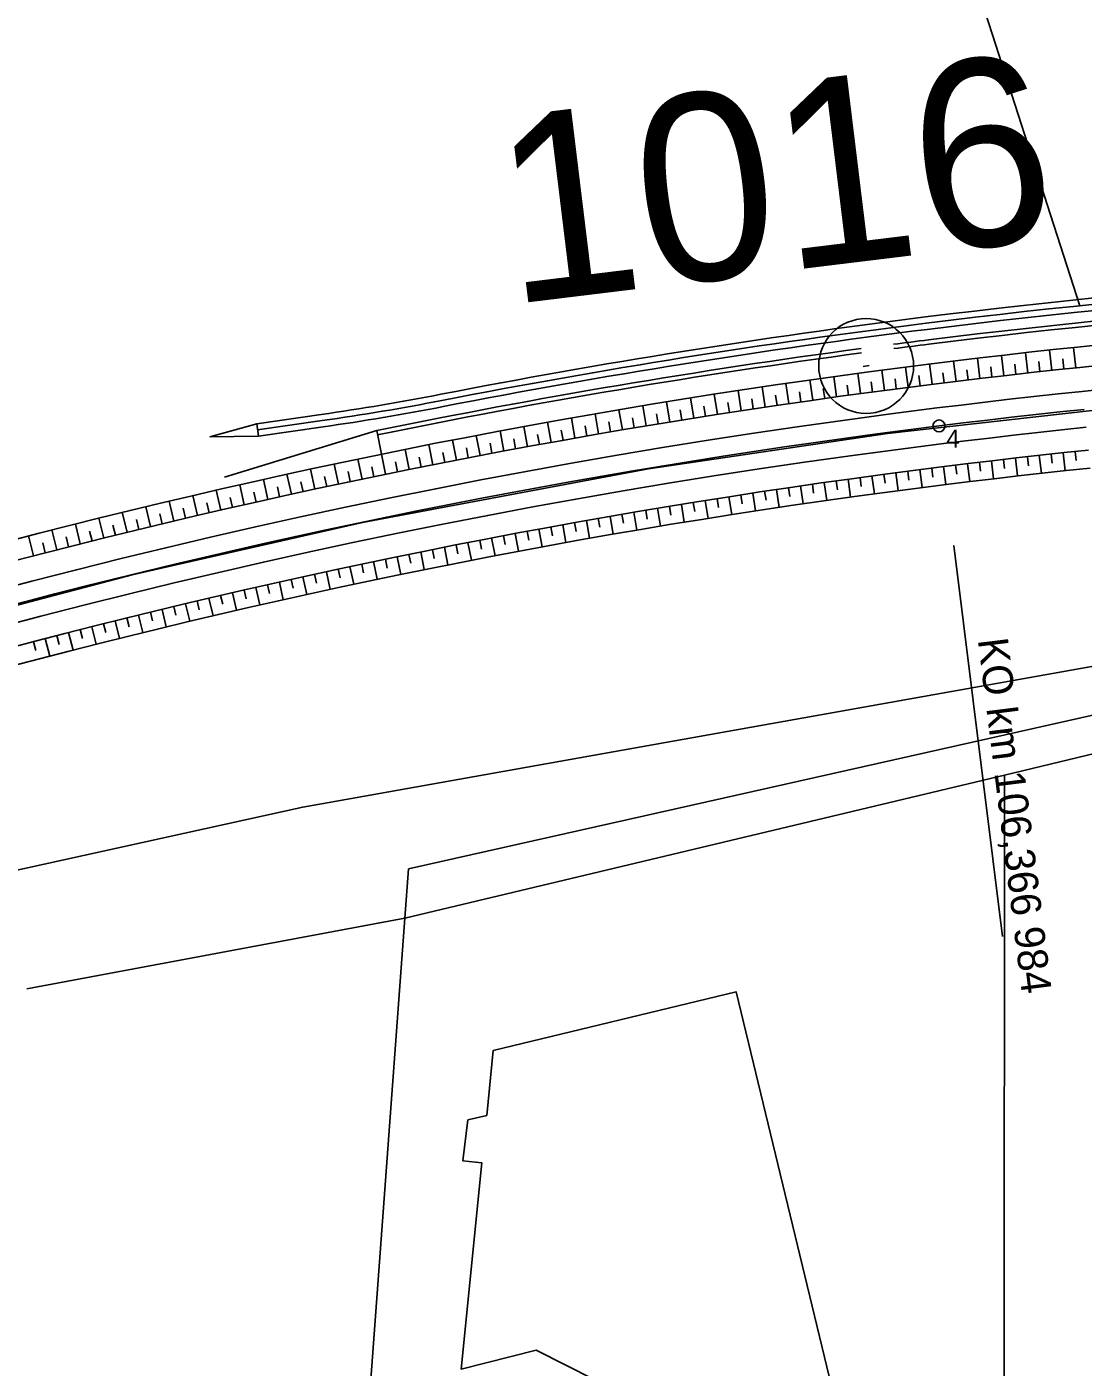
# Model space of a CAD drawing. Extents: x -758836 to -757729, y -1175316 to -1174366.
# Drawn here: x -758279.4 to -758235.6, y -1174806.2 to -1174750.5 of the extents above; entities that cross this region are included whole.
import ezdxf

# ---------------------------------------------------------------- set-up
doc = ezdxf.new("R2010")
doc.units = 0
for name, color, linetype in [('_NOR-návrh tenká', 7, 'Continuous'), ('_NOR-osa', 7, 'Continuous'), ('_NOR-popis', 7, 'Continuous'), ('_NOR-svahy', 7, 'Continuous'), ('_NOR-vytyčení', 7, 'Continuous'), ('G_Obvod stavby', 7, 'Continuous'), ('Hranice parcel', 7, 'Continuous'), ('Vrstva 1', 7, 'Continuous'), ('Vrstva 63', 7, 'Continuous')]:
    doc.layers.add(name, color=color, linetype=linetype)

# ---------------------------------------------------------------- blocks, each defined once
blk = doc.blocks.new('POINT_DISPLAY')
blk.add_line((0, 0), (0, 0))
blk = doc.blocks.new('C015_1')
at = {"layer": 'Vrstva 63'}
blk.add_line((-0.05, 0), (0.05, 0), dxfattribs=at)
blk.add_circle((0, 0), 0.756, dxfattribs=at)

msp = doc.modelspace()

# ---------------------------------------------------------------- linework, layer by layer
at = {"layer": '_NOR-návrh tenká'}
for p, q in [((-758271.812, -1174767.556), (-758269.869, -1174767.016)), ((-758269.869, -1174767.016), (-758269.795, -1174767.531)), ((-758269.795, -1174767.531), (-758271.812, -1174767.556)), ((-758271.211, -1174769.241), (-758264.887, -1174767.303)), ((-758264.887, -1174767.303), (-758264.686, -1174768.283))]:
    msp.add_line(p, q, dxfattribs=at)
for points in [[(-758242.105, -1174762.587), (-758241.09, -1174762.463), (-758240.072, -1174762.341), (-758239.053, -1174762.223), (-758238.033, -1174762.108), (-758237.014, -1174761.997), (-758235.995, -1174761.888), (-758234.975, -1174761.783)], [(-758242.073, -1174762.845), (-758241.059, -1174762.721), (-758240.041, -1174762.599), (-758239.023, -1174762.481), (-758238.005, -1174762.366), (-758236.986, -1174762.255), (-758235.968, -1174762.147), (-758234.949, -1174762.042)], [(-758242.041, -1174763.103), (-758241.028, -1174762.979), (-758240.011, -1174762.857), (-758238.994, -1174762.739), (-758237.976, -1174762.625), (-758236.958, -1174762.514), (-758235.941, -1174762.406), (-758234.923, -1174762.301)], [(-758241.988, -1174763.537), (-758240.975, -1174763.413), (-758239.96, -1174763.291), (-758238.944, -1174763.174), (-758237.928, -1174763.059), (-758236.912, -1174762.948), (-758235.895, -1174762.84), (-758234.879, -1174762.735)], [(-758241.966, -1174763.716), (-758240.954, -1174763.591), (-758239.939, -1174763.47), (-758238.923, -1174763.352), (-758237.908, -1174763.238), (-758236.892, -1174763.127), (-758235.877, -1174763.019), (-758234.861, -1174762.915)], [(-758241.865, -1174764.529), (-758240.855, -1174764.405), (-758239.843, -1174764.285), (-758238.83, -1174764.167), (-758237.818, -1174764.053), (-758236.804, -1174763.942), (-758235.791, -1174763.835), (-758234.778, -1174763.73)], [(-758241.761, -1174765.373), (-758240.753, -1174765.249), (-758239.744, -1174765.129), (-758238.734, -1174765.012), (-758237.724, -1174764.898), (-758236.713, -1174764.787), (-758235.703, -1174764.68), (-758234.692, -1174764.576)], [(-758241.638, -1174766.365), (-758240.633, -1174766.242), (-758239.627, -1174766.122), (-758238.62, -1174766.005), (-758237.613, -1174765.892), (-758236.606, -1174765.782), (-758235.599, -1174765.675), (-758234.591, -1174765.571)], [(-758269.869, -1174767.016), (-758267.19, -1174766.633)], [(-758269.832, -1174767.273), (-758267.154, -1174766.89)], [(-758269.795, -1174767.531), (-758267.117, -1174767.148)], [(-758241.454, -1174767.854), (-758240.453, -1174767.731), (-758239.452, -1174767.612), (-758238.45, -1174767.496), (-758237.448, -1174767.383), (-758236.446, -1174767.273), (-758235.443, -1174767.167)], [(-758241.337, -1174768.797), (-758240.338, -1174768.674), (-758239.341, -1174768.555), (-758238.342, -1174768.439), (-758237.343, -1174768.327), (-758236.344, -1174768.218), (-758235.344, -1174768.111)], [(-758241.245, -1174769.541), (-758240.248, -1174769.419), (-758239.253, -1174769.3), (-758238.257, -1174769.185), (-758237.26, -1174769.072), (-758236.263, -1174768.963), (-758235.266, -1174768.857)]]:
    msp.add_lwpolyline(points, dxfattribs=at)
for centre, radius, start, end in [((-758205.34, -1175057.864), 297.557, 97.09744, 101.02201), ((-758205.34, -1175057.864), 297.297, 97.09748, 101.02201), ((-758205.34, -1175057.864), 297.037, 97.09752, 101.02201), ((-758205.34, -1175057.864), 296.6, 97.09759, 97.37991), ((-758205.34, -1175057.864), 296.42, 97.09762, 97.38099), ((-758205.34, -1175057.864), 296.6, 97.64234, 101.58164), ((-758205.34, -1175057.864), 296.42, 97.64296, 101.58164), ((-758205.34, -1175057.864), 295.6, 97.09776, 129.28488), ((-758205.34, -1175057.864), 294.75, 97.0979, 129.28474), ((-758281.298, -1174667.896), 99.74, 278.13115, 281.02201), ((-758205.34, -1175057.864), 293.75, 97.09807, 120.96729), ((-758281.298, -1174667.896), 100, 278.13115, 281.02201), ((-758281.298, -1174667.896), 100.26, 278.13115, 281.02201), ((-758205.34, -1175057.864), 292.25, 97.09832, 120.96729), ((-758205.34, -1175057.864), 291.3, 97.09848, 129.28417), ((-758205.34, -1175057.864), 290.55, 97.09861, 129.28404)]:
    msp.add_arc(centre, radius, start, end, dxfattribs=at)
at = {"layer": '_NOR-osa'}
msp.add_lwpolyline([(-758235.521, -1174766.421), (-758236.526, -1174766.527), (-758237.531, -1174766.637), (-758238.535, -1174766.75), (-758239.539, -1174766.867), (-758240.543, -1174766.987), (-758241.546, -1174767.11)], dxfattribs=at)
msp.add_circle((-758241.546, -1174767.11), 0.25, dxfattribs=at)
msp.add_arc((-758205.34, -1175057.864), 293, 97.09819, 129.28445, dxfattribs=at)
at = {"layer": '_NOR-popis'}
msp.add_line((-758240.928, -1174772.071), (-758238.907, -1174788.304), dxfattribs=at)
msp.add_lwpolyline([(-758240.814, -1174715.275), (-758249.857, -1174718.187), (-758235.706, -1174762.12)], dxfattribs=at)
at = {"layer": '_NOR-svahy'}
for points in [[(-758239.845, -1174765.141), (-758239.946, -1174764.297)], [(-758238.852, -1174765.025), (-758238.95, -1174764.181)], [(-758237.858, -1174764.913), (-758237.953, -1174764.068)], [(-758236.864, -1174764.804), (-758236.956, -1174763.959)], [(-758236.367, -1174764.751), (-758236.412, -1174764.328)], [(-758235.87, -1174764.698), (-758235.959, -1174763.853)], [(-758243.814, -1174765.636), (-758243.925, -1174764.793)], [(-758242.823, -1174765.507), (-758242.931, -1174764.664)], [(-758241.83, -1174765.382), (-758241.936, -1174764.538)], [(-758241.334, -1174765.321), (-758241.386, -1174764.899)], [(-758240.838, -1174765.26), (-758240.942, -1174764.416)], [(-758240.342, -1174765.2), (-758240.392, -1174764.778)], [(-758239.348, -1174765.083), (-758239.397, -1174764.661)], [(-758238.355, -1174764.969), (-758238.402, -1174764.547)], [(-758237.361, -1174764.858), (-758237.407, -1174764.436)], [(-758247.776, -1174766.185), (-758247.899, -1174765.344)], [(-758246.787, -1174766.043), (-758246.906, -1174765.201)], [(-758245.796, -1174765.904), (-758245.913, -1174765.062)], [(-758245.301, -1174765.836), (-758245.359, -1174765.414)], [(-758244.805, -1174765.768), (-758244.919, -1174764.926)], [(-758244.31, -1174765.702), (-758244.366, -1174765.28)], [(-758243.318, -1174765.571), (-758243.373, -1174765.15)], [(-758242.327, -1174765.444), (-758242.38, -1174765.022)], [(-758251.731, -1174766.788), (-758251.864, -1174765.948)], [(-758250.743, -1174766.632), (-758250.874, -1174765.792)], [(-758249.755, -1174766.48), (-758249.883, -1174765.639)], [(-758249.26, -1174766.405), (-758249.323, -1174765.984)], [(-758248.766, -1174766.331), (-758248.891, -1174765.49)], [(-758248.271, -1174766.257), (-758248.333, -1174765.837)], [(-758247.282, -1174766.113), (-758247.342, -1174765.693)], [(-758246.291, -1174765.973), (-758246.35, -1174765.552)], [(-758254.691, -1174767.275), (-758254.833, -1174766.437)], [(-758253.705, -1174767.109), (-758253.844, -1174766.271)], [(-758252.718, -1174766.947), (-758252.855, -1174766.108)], [(-758252.224, -1174766.867), (-758252.292, -1174766.447)], [(-758251.237, -1174766.709), (-758251.303, -1174766.29)], [(-758250.249, -1174766.555), (-758250.314, -1174766.135)], [(-758258.63, -1174767.971), (-758258.783, -1174767.135)], [(-758257.646, -1174767.792), (-758257.797, -1174766.956)], [(-758256.661, -1174767.617), (-758256.809, -1174766.78)], [(-758256.169, -1174767.53), (-758256.242, -1174767.111)], [(-758255.676, -1174767.444), (-758255.822, -1174766.607)], [(-758255.184, -1174767.359), (-758255.256, -1174766.94)], [(-758254.198, -1174767.192), (-758254.268, -1174766.773)], [(-758253.211, -1174767.028), (-758253.28, -1174766.608)], [(-758261.577, -1174768.529), (-758261.74, -1174767.694)], [(-758260.595, -1174768.34), (-758260.755, -1174767.505)], [(-758259.613, -1174768.154), (-758259.769, -1174767.318)], [(-758259.121, -1174768.062), (-758259.199, -1174767.644)], [(-758258.138, -1174767.881), (-758258.214, -1174767.463)], [(-758257.154, -1174767.704), (-758257.228, -1174767.286)], [(-758263.539, -1174768.917), (-758263.707, -1174768.084)], [(-758262.559, -1174768.721), (-758262.724, -1174767.887)], [(-758262.068, -1174768.625), (-758262.15, -1174768.208)], [(-758261.087, -1174768.434), (-758261.167, -1174768.017)], [(-758260.104, -1174768.246), (-758260.183, -1174767.829)], [(-758236.387, -1174768.222), (-758236.306, -1174768.968)], [(-758235.89, -1174768.169), (-758235.851, -1174768.542)], [(-758266.477, -1174769.524), (-758266.654, -1174768.693)], [(-758265.499, -1174769.319), (-758265.672, -1174768.487)], [(-758265.009, -1174769.217), (-758265.095, -1174768.801)], [(-758264.519, -1174769.116), (-758264.69, -1174768.284)], [(-758264.029, -1174769.016), (-758264.114, -1174768.6)], [(-758263.049, -1174768.819), (-758263.132, -1174768.402)], [(-758241.354, -1174768.799), (-758241.261, -1174769.543)], [(-758240.858, -1174768.738), (-758240.812, -1174769.11)], [(-758240.362, -1174768.677), (-758240.27, -1174769.421)], [(-758239.865, -1174768.618), (-758239.821, -1174768.99)], [(-758239.369, -1174768.558), (-758239.28, -1174769.303)], [(-758238.872, -1174768.501), (-758238.829, -1174768.873)], [(-758238.375, -1174768.443), (-758238.289, -1174769.188)], [(-758237.878, -1174768.387), (-758237.836, -1174768.76)], [(-758237.382, -1174768.331), (-758237.298, -1174769.076)], [(-758236.885, -1174768.277), (-758236.844, -1174768.649)], [(-758269.409, -1174770.162), (-758269.594, -1174769.332)], [(-758268.432, -1174769.946), (-758268.614, -1174769.116)], [(-758267.455, -1174769.733), (-758267.634, -1174768.903)], [(-758266.966, -1174769.629), (-758267.055, -1174769.213)], [(-758265.988, -1174769.421), (-758266.075, -1174769.005)], [(-758245.32, -1174769.321), (-758245.217, -1174770.064)], [(-758244.825, -1174769.253), (-758244.774, -1174769.624)], [(-758244.329, -1174769.185), (-758244.229, -1174769.928)], [(-758243.834, -1174769.119), (-758243.784, -1174769.49)], [(-758243.338, -1174769.053), (-758243.24, -1174769.797)], [(-758242.842, -1174768.988), (-758242.794, -1174769.36)], [(-758242.346, -1174768.924), (-758242.251, -1174769.668)], [(-758241.85, -1174768.861), (-758241.803, -1174769.233)], [(-758271.359, -1174770.603), (-758271.55, -1174769.775)], [(-758270.385, -1174770.381), (-758270.572, -1174769.552)], [(-758269.897, -1174770.271), (-758269.99, -1174769.856)], [(-758268.921, -1174770.053), (-758269.012, -1174769.638)], [(-758267.944, -1174769.839), (-758268.034, -1174769.424)], [(-758249.278, -1174769.897), (-758249.165, -1174770.638)], [(-758248.784, -1174769.822), (-758248.728, -1174770.193)], [(-758248.289, -1174769.748), (-758248.179, -1174770.49)], [(-758247.795, -1174769.674), (-758247.74, -1174770.045)], [(-758247.3, -1174769.602), (-758247.192, -1174770.344)], [(-758246.805, -1174769.53), (-758246.752, -1174769.902)], [(-758246.31, -1174769.46), (-758246.205, -1174770.202)], [(-758245.815, -1174769.39), (-758245.763, -1174769.761)], [(-758274.28, -1174771.29), (-758274.479, -1174770.463)], [(-758273.307, -1174771.058), (-758273.503, -1174770.23)], [(-758272.334, -1174770.829), (-758272.527, -1174770.001)], [(-758271.847, -1174770.715), (-758271.943, -1174770.301)], [(-758270.872, -1174770.491), (-758270.967, -1174770.077)], [(-758252.735, -1174770.446), (-758252.674, -1174770.816)], [(-758252.241, -1174770.365), (-758252.121, -1174771.105)], [(-758251.748, -1174770.285), (-758251.688, -1174770.655)], [(-758251.254, -1174770.205), (-758251.136, -1174770.946)], [(-758250.76, -1174770.127), (-758250.702, -1174770.497)], [(-758250.266, -1174770.049), (-758250.151, -1174770.79)], [(-758249.772, -1174769.973), (-758249.715, -1174770.343)], [(-758276.223, -1174771.764), (-758276.427, -1174770.939)], [(-758275.252, -1174771.525), (-758275.453, -1174770.7)], [(-758274.766, -1174771.407), (-758274.866, -1174770.994)], [(-758273.794, -1174771.173), (-758273.892, -1174770.76)], [(-758272.821, -1174770.943), (-758272.918, -1174770.529)], [(-758256.185, -1174771.036), (-758256.054, -1174771.774)], [(-758255.692, -1174770.949), (-758255.627, -1174771.318)], [(-758255.2, -1174770.863), (-758255.071, -1174771.602)], [(-758254.707, -1174770.778), (-758254.643, -1174771.147)], [(-758254.214, -1174770.693), (-758254.088, -1174771.433)], [(-758253.721, -1174770.61), (-758253.659, -1174770.98)], [(-758253.228, -1174770.527), (-758253.105, -1174771.267)], [(-758278.162, -1174772.252), (-758278.372, -1174771.428)], [(-758277.193, -1174772.006), (-758277.4, -1174771.182)], [(-758276.708, -1174771.885), (-758276.811, -1174771.472)], [(-758275.737, -1174771.644), (-758275.839, -1174771.232)], [(-758259.136, -1174771.575), (-758258.997, -1174772.312)], [(-758258.644, -1174771.483), (-758258.576, -1174771.851)], [(-758258.153, -1174771.392), (-758258.017, -1174772.129)], [(-758257.661, -1174771.301), (-758257.594, -1174771.67)], [(-758257.169, -1174771.212), (-758257.036, -1174771.95)], [(-758256.677, -1174771.123), (-758256.611, -1174771.493)], [(-758279.131, -1174772.5), (-758279.344, -1174771.677)], [(-758278.647, -1174772.376), (-758278.752, -1174771.964)], [(-758277.678, -1174772.129), (-758277.782, -1174771.717)], [(-758262.081, -1174772.144), (-758261.935, -1174772.879)], [(-758261.591, -1174772.047), (-758261.518, -1174772.415)], [(-758261.1, -1174771.951), (-758260.957, -1174772.687)], [(-758260.609, -1174771.855), (-758260.538, -1174772.224)], [(-758260.118, -1174771.761), (-758259.977, -1174772.498)], [(-758259.627, -1174771.667), (-758259.557, -1174772.036)], [(-758264.531, -1174772.641), (-758264.455, -1174773.008)], [(-758264.042, -1174772.54), (-758263.891, -1174773.275)], [(-758263.552, -1174772.44), (-758263.477, -1174772.807)], [(-758263.062, -1174772.34), (-758262.913, -1174773.075)], [(-758262.572, -1174772.242), (-758262.498, -1174772.609)], [(-758267.466, -1174773.266), (-758267.386, -1174773.632)], [(-758266.977, -1174773.16), (-758266.818, -1174773.893)], [(-758266.488, -1174773.054), (-758266.41, -1174773.421)], [(-758265.999, -1174772.95), (-758265.843, -1174773.683)], [(-758265.51, -1174772.846), (-758265.433, -1174773.213)], [(-758265.021, -1174772.743), (-758264.867, -1174773.477)], [(-758269.906, -1174773.81), (-758269.74, -1174774.541)], [(-758269.418, -1174773.699), (-758269.336, -1174774.065)], [(-758268.93, -1174773.59), (-758268.767, -1174774.322)], [(-758268.442, -1174773.481), (-758268.361, -1174773.847)], [(-758267.954, -1174773.373), (-758267.793, -1174774.106)], [(-758272.341, -1174774.374), (-758272.255, -1174774.739)], [(-758271.854, -1174774.26), (-758271.683, -1174774.99)], [(-758271.368, -1174774.146), (-758271.283, -1174774.511)], [(-758270.88, -1174774.033), (-758270.712, -1174774.764)], [(-758270.393, -1174773.921), (-758270.309, -1174774.286)], [(-758274.286, -1174774.841), (-758274.197, -1174775.205)], [(-758273.8, -1174774.723), (-758273.624, -1174775.452)], [(-758273.314, -1174774.606), (-758273.226, -1174774.971)], [(-758272.828, -1174774.49), (-758272.654, -1174775.219)], [(-758276.712, -1174775.443), (-758276.529, -1174776.17)], [(-758276.227, -1174775.321), (-758276.136, -1174775.685)], [(-758275.742, -1174775.2), (-758275.561, -1174775.927)], [(-758275.257, -1174775.079), (-758275.167, -1174775.443)], [(-758274.772, -1174774.96), (-758274.593, -1174775.688)], [(-758278.65, -1174775.94), (-758278.461, -1174776.666)], [(-758278.166, -1174775.814), (-758278.072, -1174776.177)], [(-758277.681, -1174775.69), (-758277.495, -1174776.416)], [(-758277.197, -1174775.566), (-758277.104, -1174775.929)], [(-758279.133, -1174776.066), (-758279.038, -1174776.429)]]:
    msp.add_lwpolyline(points, dxfattribs=at)
at = {"layer": 'G_Obvod stavby'}
msp.add_lwpolyline([(-758392.72, -1174840.756), (-758391.23, -1174838.56), (-758368.37, -1174821.64), (-758340.31, -1174807.33), (-758320.27, -1174796.89), (-758301, -1174790.21), (-758267.96, -1174782.93), (-758224.96, -1174775.27), (-758184.87, -1174772.83), (-758142.71, -1174770.26), (-758089.84, -1174768.68), (-758106.02, -1174731.44), (-758149.09, -1174725.67), (-758199.62, -1174726.6), (-758225.76, -1174732.36), (-758252.17, -1174738.18), (-758254.97, -1174739.34), (-758266.58, -1174744.16), (-758279.45, -1174749.49), (-758302.42, -1174759.02), (-758331.68, -1174770.24), (-758367.17, -1174799.81), (-758405.64, -1174832.2)], dxfattribs=at)
at = {"layer": 'Hranice parcel'}
for p, q in [((-758225.62, -1174776.96), (-758263.57, -1174785.5)), ((-758238.83, -1174781.6), (-758263.72, -1174787.54)), ((-758238.83, -1174781.6), (-758238.86, -1174825.45)), ((-758263.57, -1174785.5), (-758263.72, -1174787.54)), ((-758263.72, -1174787.54), (-758279.42, -1174790.47)), ((-758263.72, -1174787.54), (-758266.21, -1174821.26))]:
    msp.add_line(p, q, dxfattribs=at)
for points in [[(-758184.87, -1174772.83), (-758224.96, -1174775.27), (-758267.96, -1174782.93), (-758301, -1174790.21), (-758320.27, -1174796.89)], [(-758225.53, -1174779.72), (-758235.04, -1174780.69), (-758238.83, -1174781.6)], [(-758261.31, -1174797.61), (-758261.1, -1174795.92), (-758260.32, -1174795.73), (-758260.05, -1174793.03), (-758249.97, -1174790.6), (-758245.99, -1174807.02), (-758245.12, -1174810.68), (-758252.37, -1174812.37), (-758253.43, -1174807.62), (-758255.84, -1174806.71), (-758258.27, -1174805.48), (-758261.38, -1174806.26), (-758260.52, -1174797.7), (-758261.31, -1174797.61)]]:
    msp.add_lwpolyline(points, dxfattribs=at)
at = {"layer": 'Vrstva 1'}
for points in [[(-758275.047, -1174773.289), (-758265.484, -1174771.118), (-758253.61, -1174768.888), (-758243.69, -1174767.426), (-758231.371, -1174766.042), (-758219.363, -1174765.122), (-758206.915, -1174764.505), (-758194.225, -1174764.118), (-758182.013, -1174763.871), (-758170.862, -1174763.683), (-758162.019, -1174763.496), (-758153.195, -1174763.228), (-758152.069, -1174763.19), (-758141.836, -1174762.716), (-758130.402, -1174761.933), (-758120.726, -1174760.981), (-758108.612, -1174759.398), (-758096.467, -1174757.277), (-758085.591, -1174754.917)], [(-758443.817, -1174881.252), (-758441.673, -1174879.1), (-758423.412, -1174860.854), (-758412.446, -1174850.23), (-758405.322, -1174843.614), (-758399.028, -1174837.996), (-758392.64, -1174832.554), (-758380.106, -1174822.693), (-758371.773, -1174816.721), (-758363.37, -1174811.125), (-758354.46, -1174805.649), (-758345.526, -1174800.592), (-758336.614, -1174795.909), (-758327.338, -1174791.462), (-758317.813, -1174787.314), (-758307.666, -1174783.315), (-758298.059, -1174779.921), (-758285.017, -1174775.914), (-758275.047, -1174773.289)]]:
    msp.add_lwpolyline(points, dxfattribs=at)

# ---------------------------------------------------------------- block references
at = {"layer": '_NOR-vytyčení'}
msp.add_blockref('POINT_DISPLAY', (-758241.546, -1174767.11), dxfattribs=at)
at = {"layer": 'Vrstva 63', "xscale": 2.6043784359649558, "yscale": 2.6043784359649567, "rotation": 6.9610704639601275}
msp.add_blockref('C015_1', (-758244.571, -1174764.621), dxfattribs=at)

# ---------------------------------------------------------------- texts
at = {"layer": '_NOR-popis'}
msp.add_text('KO km 106,366 984', height=1.25, rotation=277.0982, dxfattribs=at).set_placement((-758239.938, -1174775.979))
at = {"layer": '_NOR-vytyčení'}
msp.add_text('4', height=0.75, rotation=360, dxfattribs=at).set_placement((-758241.246, -1174768.01))
at = {"layer": 'Vrstva 63'}
msp.add_text('1016', height=7.7553, rotation=6.9611, dxfattribs=at).set_placement((-758259.38, -1174762.073))

doc.saveas('drawing.dxf')
